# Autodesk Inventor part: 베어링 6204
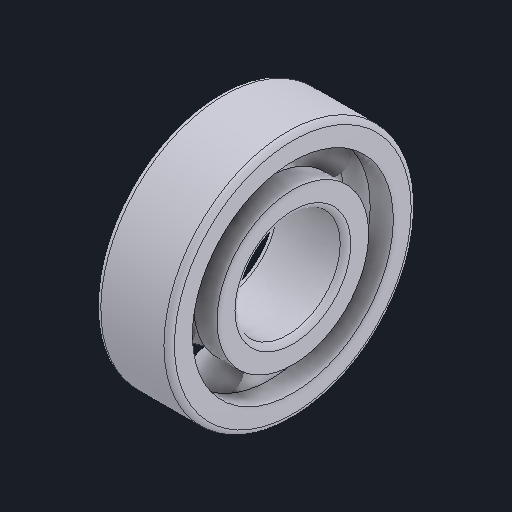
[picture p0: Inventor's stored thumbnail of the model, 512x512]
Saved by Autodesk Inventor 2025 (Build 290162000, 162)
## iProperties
Created: 2025-08
Part Number: 베어링 6204
Material: 강철, 연강
Description: 깊은 그루브 볼 베어링
Document SubType Name: Modeling
Designer: infra023
Density: 7.86 g/cm^3
Appearance: 기본값
Author: jhkim
Sending System: Autodesk Inventor 2026
Preprocessor: ST-DEVELOPER v20.1
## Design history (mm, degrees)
feature "Solid1"
feature "Solid1:1"
feature "Solid1:2"
feature "Solid1:3"
feature "Solid1:4"
feature "Solid1:5"
feature "Solid1:6"
feature "Solid1:7"
feature "Solid1:8"
node "솔리드1"
node "솔리드2"
node "솔리드3"
node "솔리드4"
node "솔리드5"
node "솔리드6"
node "솔리드7"
node "솔리드8"
node "솔리드9"
